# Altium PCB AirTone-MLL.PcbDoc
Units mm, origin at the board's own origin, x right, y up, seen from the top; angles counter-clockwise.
Board outline 33.13 x 51.18 mm, 2 copper layers (Top Layer, Bottom Layer); 97 components, 78 nets, 367 pads, 121 vias.
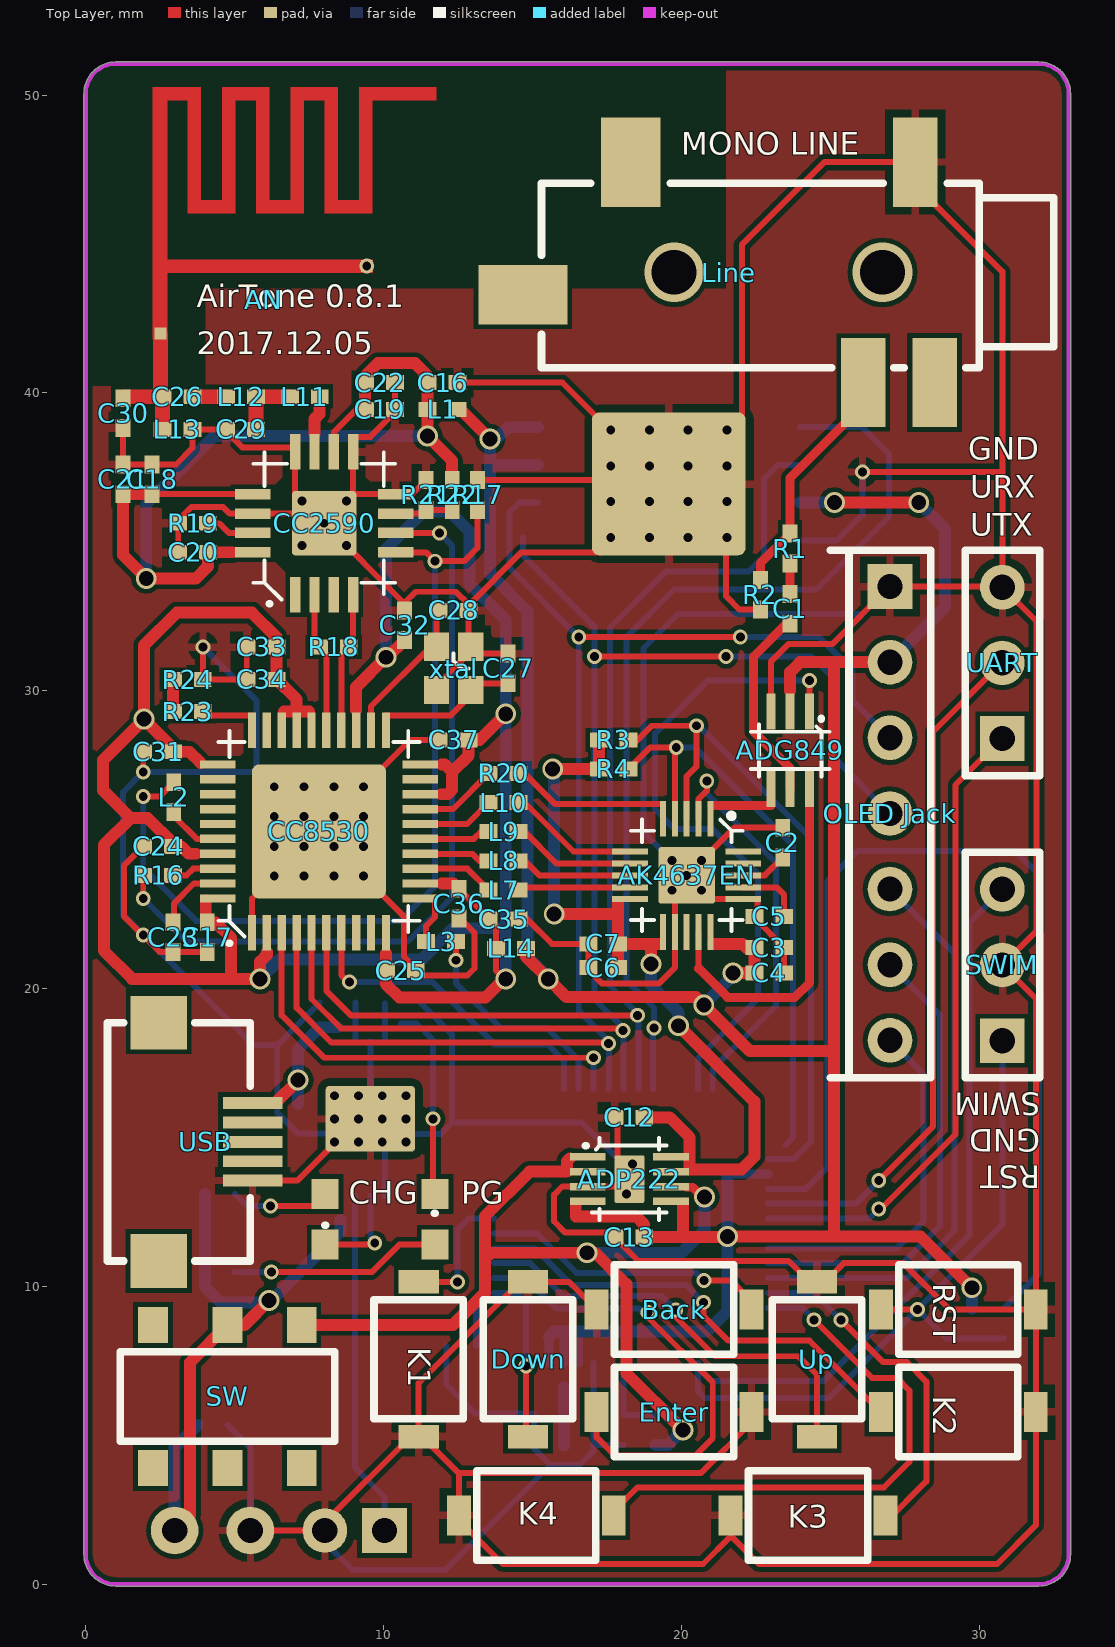
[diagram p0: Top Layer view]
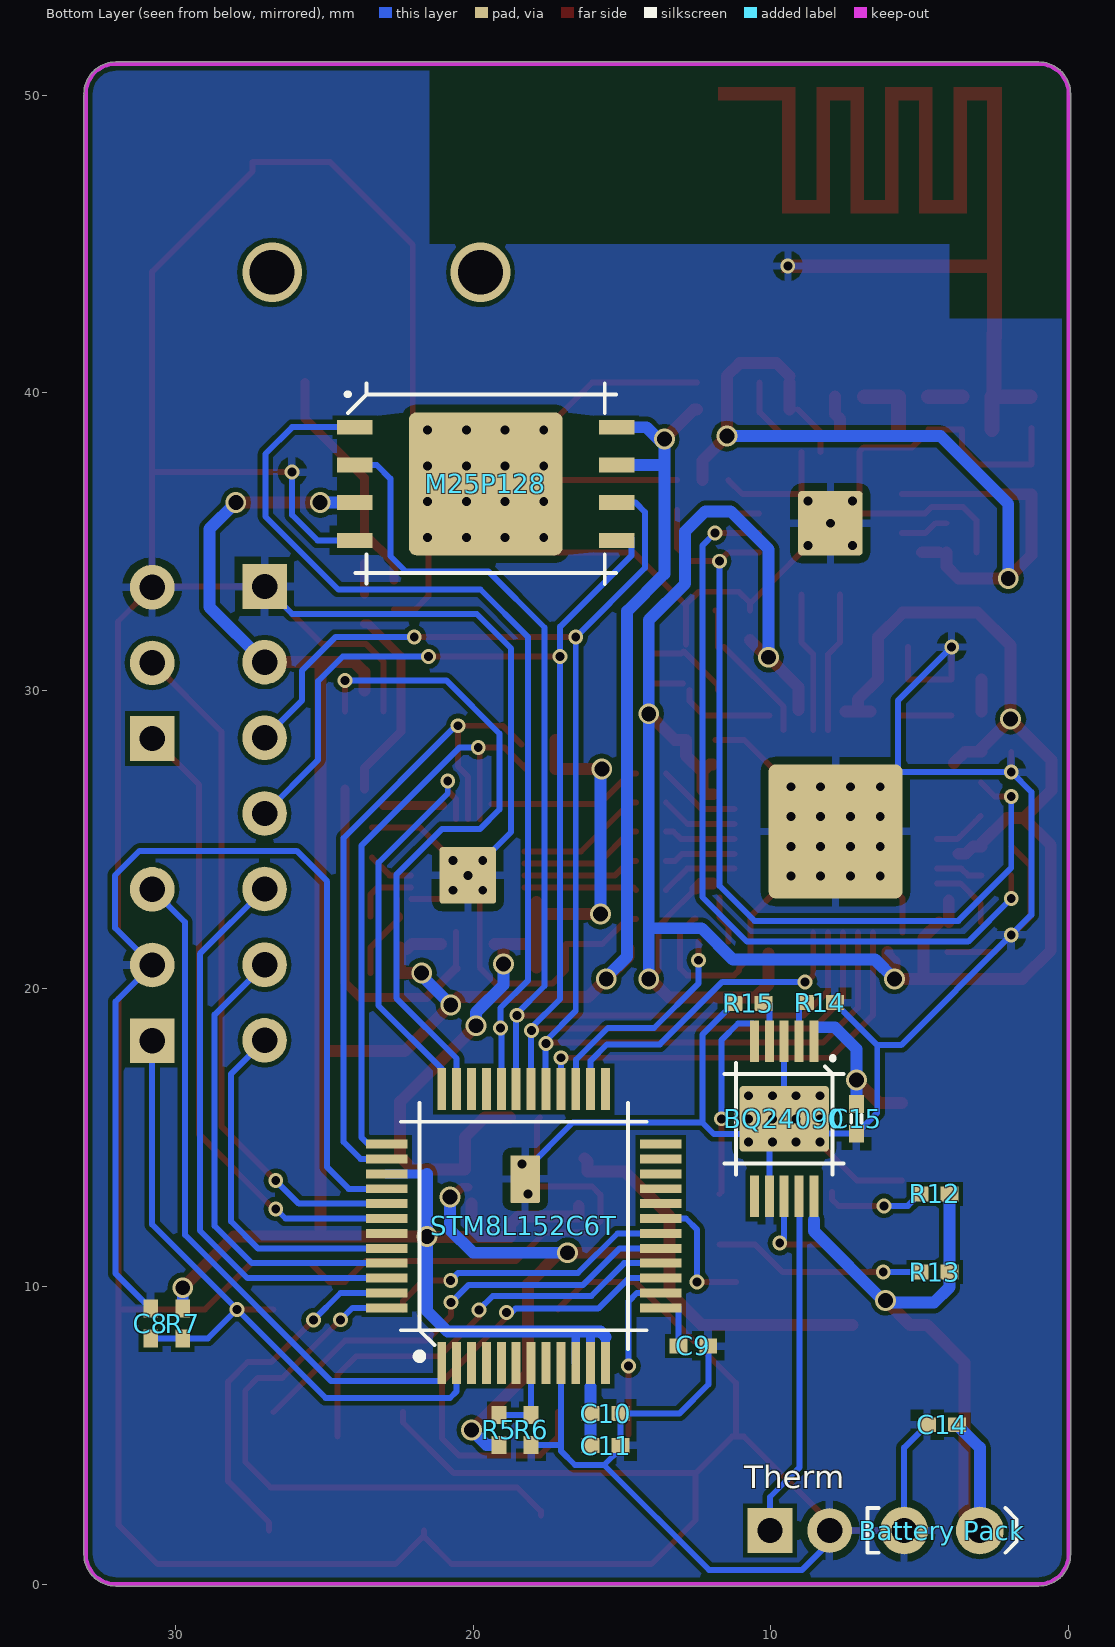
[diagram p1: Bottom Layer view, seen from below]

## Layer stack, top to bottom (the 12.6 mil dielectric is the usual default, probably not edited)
Top Solder: solder mask 0.0102, Solder Resist, Dk 3.5
Top Layer: signal copper 0.0356
Dielectric 1: dielectric 0.32, FR-4, Dk 4.8
Bottom Layer: signal copper 0.0356
Bottom Solder: solder mask 0.0102, Solder Resist, Dk 3.5

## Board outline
-0.065,1 -0.065,50 cw(c0,50) -0.06,50.025 cw(c0,50.05) -0.065,50.05 cw(c1,50.05) 1,51.115 32,51.115 cw(c32,50.05) 33.065,50.05 cw(c33,50.05) 33.06,50.025 cw(c33,50) 33.065,50 33.065,1 cw(c32,1) 32,-0.065 1,-0.065 cw(c1,1)

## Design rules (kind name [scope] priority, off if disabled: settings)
Clearance [All] p1: gap=0.16
Clearance poly [InPoly] p2: gap=2
ComponentClearance [All] p1: gap=-1 collisioncheckmode=3 verticalgap=0.254 showdistances=FALSE
HoleToHoleClearance [All] p1: gap=0.01 allowstackedmicrovias=TRUE
MinimumSolderMaskSliver [All] p1: minsoldermaskwidth=0.01
PlaneClearance [All] p1: clearance=0.58
PolygonConnect [All] p1: connectstyle=Relief reliefconductorwidth=0.254 reliefentries=4 polygonreliefangle="90 Angle" airgapwidth=0.254
RoutingVias [All] p1: holewidth=0.3 width=0.4 viastyle="Through Hole" minholewidth=0.3 minwidth=0.4 maxholewidth=5 maxwidth=6
SilkToSilkClearance [All] p1: silktosilkclearance=0
SilkToSolderMaskClearance [IsPad] p1: minsilkscreentomaskgap=0 clearancetoexposedcopper=TRUE
SolderMaskExpansion [All] p1: expansion=0.102
Width [All] p1: maxlimit=0.8 minlimit=0.1 preferedwidth=0.2
24 further rules are at their usual default settings.

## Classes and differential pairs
component class Audio: ADG849 AK4637EN C1 C2 C3 C4 C5 C6 C7 Line R1 R2 R3 R4
component class MCU: ADP222 Back "Battery Pack" BQ24090 C8 C9 C10 C11 C12 C13 C14 C15 CHG Down Enter K1 K2 K3 K4 M25P128 "OLED Jack" PG R5 R6 R7 R12 R13 R14 R15 RST STM8L152C6T SW SWIM Therm UART Up USB
component class RF: AN C16 C17 C18 C19 C20 C21 C22 C23 C24 C25 C26 C27 C28 C29 C30 C31 C32 C33 C34 C35 C36 C37 CC2590 CC8530 L1 L2 L3 L7 L8 L9 L10 L11 L12 L13 L14 R16 R17 R18 R19 R20 R21 R22 R23 R24 X1 xtal

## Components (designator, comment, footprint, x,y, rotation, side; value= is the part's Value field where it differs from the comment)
ADG849 "ADG849" ADG849 23.65,28 r180 top
ADP222 "ADP222ACPZ-1833-R7" ADP22x 18.25,13.6 r270 top
AK4637EN "AK4637EN" AK4637EN 20.175,23.8 r180 top
AN "Antenna" ANT_WIGGLE_1MM 2.5,42 r0 top
Back "Button" Button_3x4 19.75,9.225 r180 top
"Battery Pack" "Battery Pack" "Battery Jack small" 4.25,1.8 r0 bottom
BQ24090 "BQ24090" BQ24090 9.55,15.625 r0 bottom
C1 "Capacity SMD" "SMD 0402" 23.65,32.75 r90 top
C2 "Capacity SMD" "SMD 0402" 23.4,24.9 r90 top
C3 "Capacity SMD" "SMD 0402" 22.95,21.375 r0 top
C4 "Capacity SMD" "SMD 0402" 22.95,20.525 r0 top
C5 "Capacity SMD" "SMD 0402" 22.95,22.425 r180 top
C6 "Capacity SMD" "SMD 0402" 17.375,20.7 r180 top
C7 "Capacity SMD" "SMD 0402" 17.375,21.5 r180 top
C8 "Capacity SMD" "SMD 0402" 30.825,8.75 r270 bottom
C9 "Capacity SMD" "SMD 0402" 12.6,8 r0 bottom
C10 "Capacity SMD" "SMD 0402" 15.55,5.725 r0 bottom
C11 "Capacity SMD" "SMD 0402" 15.55,4.65 r0 bottom
C12 "Capacity SMD" "SMD 0402" 18.25,15.675 r180 top
C13 "Capacity SMD" "SMD 0402" 18.25,11.65 r0 top
C14 "Capacity SMD" "SMD 0402" 4.25,5.35 r180 bottom
C15 "Capacity SMD" "SMD 0402_silk" 7.125,15.625 r90 bottom
C16 "Capacity SMD" "SMD 0402" 11.975,40.35 r180 top
C17 "Capacity SMD" "SMD 0402" 4.075,21.725 r270 top
C18 "Capacity SMD" "SMD 0402" 2.225,37.1 r270 top
C19 "Capacity SMD" "SMD 0402" 9.875,39.45 r180 top
C20 "Capacity SMD" "SMD 0402" 3.6,34.65 r0 top
C21 "Capacity SMD" "SMD 0402" 1.25,37.1 r270 top
C22 "Capacity SMD" "SMD 0402" 9.875,40.35 r180 top
C23 "Capacity SMD" "SMD 0402" 2.925,21.725 r270 top
C24 "Capacity SMD" "SMD 0402" 2.425,24.775 r0 top
C25 "Capacity SMD" "SMD 0402" 10.575,20.6 r180 top
C26 "Capacity SMD" "SMD 0402" 3.075,39.875 r180 top
C27 "Capacity SMD" "SMD 0402" 14.175,30.75 r270 top
C28 "Capacity SMD" "SMD 0402" 12.35,32.7 r180 top
C29 "Capacity SMD" "SMD 0402" 5.212,38.775 r0 top
C30 "Capacity SMD" "SMD 0402" 1.25,39.325 r90 top
C31 "Capacity SMD" "SMD 0402" 2.425,27.95 r0 top
C32 "Capacity SMD" "SMD 0402" 10.7,32.2 r270 top
C33 "Capacity SMD" "SMD 0402" 5.9,31.475 r0 top
C34 "Capacity SMD" "SMD 0402" 5.9,30.383 r0 top
C35 "Capacity SMD" "SMD 0402" 14.025,22.329 r180 top
C36 "Capacity SMD" "SMD 0402" 12.525,22.85 r90 top
C37 "Capacity SMD" "SMD 0402" 12.35,28.35 r0 top
CC2590 "CC2590" CC2590 8,35.625 r90 top
CC8530 "CC8530" CC8530 7.825,25.275 r90 top
CHG "LED" LED_0603 8.025,12.25 r270 top
Down "Button" Button_3x4 14.85,7.55 r90 top
Enter "Button" Button_3x4 19.75,5.775 r0 top
K1 "Button" Button_3x4 11.175,7.55 r270 top
K2 "Button" Button_3x4 29.3,5.775 r0 top
K3 "Button" Button_3x4 24.25,2.3 r180 top
K4 "Button" Button_3x4 15.125,2.3 r180 top
L1 "Inductor SMD" "SMD 0402" 11.975,39.45 r180 top
L2 "Inductor SMD" "SMD 0402" 2.95,26.425 r90 top
L3 "Inductor SMD" "SMD 0402" 11.925,21.575 r0 top
L7 "Inductor SMD" "SMD 0402" 14.025,23.308 r180 top
L8 "Inductor SMD" "SMD 0402" 14.025,24.287 r180 top
L9 "Inductor SMD" "SMD 0402" 14.025,25.267 r180 top
L10 "Inductor SMD" "SMD 0402" 14.025,26.246 r180 top
L11 "Inductor SMD" "SMD 0402" 7.35,39.875 r0 top
L12 "Inductor SMD" "SMD 0402" 5.212,39.875 r180 top
L13 "Inductor SMD" "SMD 0402" 3.075,38.775 r180 top
L14 "Inductor SMD" "SMD 0402" 14.275,21.35 r180 top
Line "Audio Jack" "Audio Jack PJ-328" 30,44.05 r180 top
M25P128 "M25P128" M25P128 19.575,36.95 r180 bottom
"OLED Jack" "OLED Jack" "OLED Jack" 27,33.5 r0 top
PG "LED" LED_0603 11.725,12.25 r90 top
R1 "Resistor SMD" "SMD 0402" 23.65,34.775 r90 top
R2 "Resistor SMD" "SMD 0402" 22.65,33.225 r90 top
R3 "Resistor SMD" "SMD 0402" 17.725,28.35 r180 top
R4 "Resistor SMD" "SMD 0402" 17.725,27.375 r180 top
R5 "Resistor SMD" "SMD 0402" 19.125,5.175 r270 bottom
R6 "Resistor SMD" "SMD 0402" 18.05,5.175 r90 bottom
R7 "Resistor SMD" "SMD 0402" 29.75,8.75 r90 bottom
R12 "Resistor SMD" "SMD 0402" 4.5,13.1 r180 bottom
R13 "Resistor SMD" "SMD 0402" 4.5,10.475 r180 bottom
R14 "Resistor SMD" "SMD 0402" 8.35,19.525 r0 bottom
R15 "Resistor SMD" "SMD 0402" 10.75,19.5 r180 bottom
R16 "Resistor SMD" "SMD 0402" 2.425,23.8 r180 top
R17 "Resistor SMD" "SMD 0402" 13.15,36.575 r270 top
R18 "Resistor SMD" "SMD 0402" 8.325,31.475 r180 top
R19 "Resistor SMD" "SMD 0402" 3.6,35.625 r180 top
R20 "Resistor SMD" "SMD 0402" 14.025,27.225 r180 top
R21 "Resistor SMD" "SMD 0402" 11.425,36.575 r270 top
R22 "Resistor SMD" "SMD 0402" 12.3,36.575 r270 top
R23 "Resistor SMD" "SMD 0402" 3.425,29.3 r0 top
R24 "Resistor SMD" "SMD 0402" 3.425,30.375 r180 top
RST "Button" Button_3x4 29.3,9.225 r180 top
STM8L152C6T "STM8L152C6T" "STM LQFP48" 18.3,12.025 r180 bottom (schematic designator STM1)
SW "Switch" "Switch 2P2T" 4.75,6.3 r0 top
SWIM "Header_3x1" HEADER_3x1_2.54 30.775,18.25 r90 top
Therm "Thermistor" Header_2x1_2.00 9.025,1.8 r180 bottom
UART "Header_3x1" HEADER_3x1_2.54 30.775,28.395 r90 top
Up "Button" Button_3x4 24.55,7.55 r90 top
USB "USB Jack Mirco-B" "USB Micro-B" 5.275,14.85 r270 top
xtal "XTAL" xtal_3225_FA-128 12.35,30.75 r90 top

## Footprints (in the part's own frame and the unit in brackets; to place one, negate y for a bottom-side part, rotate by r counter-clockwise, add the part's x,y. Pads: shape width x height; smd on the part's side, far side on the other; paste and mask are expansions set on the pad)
ADG849 [mm]
  rect 0.3x1.2 smd paste+0 mask+0: 1(-0.65,-1.3) 2(0,-1.3) 3(0.65,-1.3) 4(0.65,1.3) 5(0,1.3) 6(-0.65,1.3)
  silkscreen extent -1.33,-1.07 1.33,0.87
ADP22x [mm]
  rect 0.25x1.2 smd mask+0: 1(-0.75,-1.4) 2(-0.25,-1.4) 3(0.25,-1.4) 4(0.75,-1.4) 5(0.75,1.4) 6(0.25,1.4) 7(-0.25,1.4) 8(-0.75,1.4)
  rrect10% 1.6x1 smd mask+0: 3(0,0)
  rrect10% 1.6x1 smd far side mask+0: 3(0,0)
  silkscreen extent -1.38,-1.48 1.38,1.25
AK4637EN [mm]
  rect 0.2x1.2 smd mask+0: 1(-0.8,-1.9) 2(-0.4,-1.9) 3(0,-1.9) 4(0.4,-1.9) 5(0.8,-1.9) 11(0.8,1.9) 12(0.4,1.9) 13(0,1.9) 14(-0.4,1.9) 15(-0.8,1.9)
  rect 1.2x0.2 smd mask+0: 6(1.9,-0.8) 7(1.9,-0.4) 8(1.9,0) 9(1.9,0.4) 10(1.9,0.8) 16(-1.9,0.8) 17(-1.9,0.4) 18(-1.9,0) 19(-1.9,-0.4) 20(-1.9,-0.8)
  rrect10% 1.9x1.9 smd mask+0: 12(0,0)
  rrect10% 1.9x1.9 smd far side mask+0: 12(0,0)
  silkscreen extent -1.88,-2.05 1.88,1.88
ANT_WIGGLE_1MM [mm]
  rect 0.4x0.4 smd: 1(0,0) 2(6.93,2.26)
  Top Layer region: 6.667,7.826 9.267,7.826 9.267,8.275 6.667,8.275
  Top Layer region: 6.667,4.024 7.117,4.024 7.117,8.275 6.667,8.275
  Top Layer region: 5.519,4.024 7.117,4.024 7.117,4.475 5.519,4.475
  Top Layer region: 5.519,4.024 5.969,4.024 5.969,8.277 5.519,8.277
  Top Layer region: 4.367,7.824 5.969,7.824 5.969,8.277 4.367,8.277
  Top Layer region: 4.367,4.024 4.818,4.024 4.818,8.274 4.367,8.274
  Top Layer region: 3.217,4.024 4.818,4.024 4.818,4.475 3.217,4.475
  Top Layer region: 3.217,4.024 3.668,4.024 3.668,8.274 3.217,8.274
  Top Layer region: 2.067,7.824 3.668,7.824 3.668,8.274 2.067,8.274
  Top Layer region: 2.067,4.026 2.517,4.026 2.517,8.274 2.067,8.274
  Top Layer region: 0.917,4.026 2.517,4.026 2.517,4.476 0.917,4.476
  Top Layer region: 0.917,4.026 1.363,4.026 1.363,8.279 0.917,8.279
  Top Layer region: -0.262,7.825 1.363,7.825 1.363,8.274 -0.262,8.274
  Top Layer region: 0.017,2.026 7.147,2.026 7.147,2.475 0.017,2.475
  Top Layer region: -0.262,-0.199 0.238,-0.199 0.238,8.274 -0.262,8.274
"Audio Jack PJ-328" [mm]
  rect 1.5x3 smd mask+0.1: 1(2.15,-3.7) 3(3.9,3.7) 5(1.5,3.7)
  rect 2x3 smd mask+0.1: 2(11.7,-3.7)
  rect 3x2 smd mask+0.1: 4(15.325,0.75)
  silkscreen extent -2.5,-3 14.7,3.2
"Battery Jack small" [mm]
  round 1.6 hole 0.85 paste+0 mask+0: 1(-1.27,0) 2(1.27,0)
  silkscreen extent -2.5,-0.75 2.5,0.75
BQ24090 [mm]
  rect 0.3x1.4 smd paste+0 mask+0: 1(-1,-2.6) 2(-0.5,-2.6) 3(0,-2.6) 4(0.5,-2.6) 5(1,-2.6) 6(1,2.6) 7(0.5,2.6) 8(0,2.6) 9(-0.5,2.6) 10(-1,2.6)
  rrect10% 3x2.2 smd far side paste+0 mask+0: 3(0,0)
  rrect10% 3x2.2 smd paste+0 mask+0: 3(0,0)
  silkscreen extent -2,-2.05 2,1.88
Button_3x4 [mm]
  rect 0.8x1.35 smd paste+0 mask+0: 1(-2.6,0) 2(2.6,0)
  silkscreen extent -2,-1.5 2,1.5
CC2590 [mm]
  rect 1.2x0.35 smd paste+0 mask+0: 1(-2.4,0.975) 2(-2.4,0.325) 3(-2.4,-0.325) 4(-2.4,-0.975) 9(2.4,-0.975) 10(2.4,-0.325) 11(2.4,0.325) 12(2.4,0.975)
  rect 0.35x1.2 smd paste+0 mask+0: 5(-0.975,-2.4) 6(-0.325,-2.4) 7(0.325,-2.4) 8(0.975,-2.4) 13(0.975,2.4) 14(0.325,2.4) 15(-0.325,2.4) 16(-0.975,2.4)
  rrect10% 2.16x2.16 smd paste+0 mask+0: 17(0,0)
  rrect10% 2.16x2.16 smd far side paste+0 mask+0: 17(0,0)
  silkscreen extent -2.7,-2.37 2.37,2.37
CC8530 [mm]
  rect 1.2x0.28 smd paste+0 mask+0: 1(-3.4,2.25) 2(-3.4,1.75) 3(-3.4,1.25) 4(-3.4,0.75) 5(-3.4,0.25) 6(-3.4,-0.25) 7(-3.4,-0.75) 8(-3.4,-1.25) 9(-3.4,-1.75) 10(-3.4,-2.25) 21(3.4,-2.25) 22(3.4,-1.75) 23(3.4,-1.25) 24(3.4,-0.75) 25(3.4,-0.25) 26(3.4,0.25) 27(3.4,0.75) 28(3.4,1.25) 29(3.4,1.75) 30(3.4,2.25)
  rect 0.28x1.2 smd paste+0 mask+0: 11(-2.25,-3.4) 12(-1.75,-3.4) 13(-1.25,-3.4) 14(-0.75,-3.4) 15(-0.25,-3.4) 16(0.25,-3.4) 17(0.75,-3.4) 18(1.25,-3.4) 19(1.75,-3.4) 20(2.25,-3.4) 31(2.25,3.4) 32(1.75,3.4) 33(1.25,3.4) 34(0.75,3.4) 35(0.25,3.4) 36(-0.25,3.4) 37(-0.75,3.4) 38(-1.25,3.4) 39(-1.75,3.4) 40(-2.25,3.4)
  rrect10% 4.5x4.5 smd paste+0 mask+0: 41(0,0)
  rrect10% 4.5x4.5 smd far side paste+0 mask+0: 41(0,0)
  silkscreen extent -3.75,-3.37 3.37,3.37
Header_2x1_2.00 [mm]
  rect 1.5x1.5 hole 0.85 paste+0 mask+0: 1(-1,0)
  round 1.5 hole 0.85 paste+0 mask+0: 2(1,0)
HEADER_3x1_2.54 [mm]
  rect 1.5x1.5 hole 0.85 paste+0 mask+0: 1(0,0)
  round 1.5 hole 0.85 paste+0 mask+0: 2(2.54,0) 3(5.08,0)
  silkscreen extent -1.25,-1.25 6.33,1.25
LED_0603 [mm]
  rect 1x0.9 smd paste+0 mask+0: 1(-0.85,0)
  rect 1x0.9 smd mask+0: 2(0.85,0)
  silkscreen extent 0.2,0 0.2,0.03
M25P128 [mm]
  rect 1.2x0.5 smd paste+0 mask+0: 1(-4.4,1.9) 2(-4.4,0.633) 3(-4.4,-0.633) 4(-4.4,-1.9) 5(4.4,-1.9) 6(4.4,-0.633) 7(4.4,0.633) 8(4.4,1.9)
  rrect10% 5.16x4.8 smd far side paste+0 mask+0: 4(0,0)
  rrect10% 5.16x4.8 smd paste+0 mask+0: 4(0,0)
  silkscreen extent -4.65,-3.37 4.38,3.37
"OLED Jack" [mm]
  rect 1.5x1.5 hole 0.85 paste+0 mask+0: 1(0,0)
  round 1.5 hole 0.85 paste+0 mask+0: 2(0,-2.54) 3(0,-5.08) 4(0,-7.62) 5(0,-10.16) 6(0,-12.7) 7(0,-15.24)
  silkscreen extent -2,-16.5 1.38,1.22
"SMD 0402" [mm]
  rect 0.6x0.5 smd paste+0 mask+0: 1(-0.5,0) 2(0.5,0)
"SMD 0402_silk" [mm]
  rect 0.6x0.5 smd paste+0 mask+0: 1(-0.5,0) 2(0.5,0)
  silkscreen extent -0.13,-0.18 0.13,0.18
"STM LQFP48" [mm] "48-Pin LQFP"
  rect 0.3x1.4 smd paste+0 mask+0: 1(-2.75,-4.6) 2(-2.25,-4.6) 3(-1.75,-4.6) 4(-1.25,-4.6) 5(-0.75,-4.6) 6(-0.25,-4.6) 7(0.25,-4.6) 8(0.75,-4.6) 9(1.25,-4.6) 10(1.75,-4.6) 11(2.25,-4.6) 12(2.75,-4.6) 25(2.75,4.6) 26(2.25,4.6) 27(1.75,4.6) 28(1.25,4.6) 29(0.75,4.6) 30(0.25,4.6) 31(-0.25,4.6) 32(-0.75,4.6) 33(-1.25,4.6) 34(-1.75,4.6) 35(-2.25,4.6) 36(-2.75,4.6)
  rect 1.4x0.3 smd paste+0 mask+0: 13(4.6,-2.75) 14(4.6,-2.25) 15(4.6,-1.75) 16(4.6,-1.25) 17(4.6,-0.75) 18(4.6,-0.25) 19(4.6,0.25) 20(4.6,0.75) 21(4.6,1.25) 22(4.6,1.75) 23(4.6,2.25) 24(4.6,2.75) 37(-4.6,2.75) 38(-4.6,2.25) 39(-4.6,1.75) 40(-4.6,1.25) 41(-4.6,0.75) 42(-4.6,0.25) 43(-4.6,-0.25) 44(-4.6,-0.75) 45(-4.6,-1.25) 46(-4.6,-1.75) 47(-4.6,-2.25) 48(-4.6,-2.75)
  silkscreen extent -4.13,-4.47 4.13,4.13
"Switch 2P2T" [mm]
  rect 1x1.2 smd: 1(-2.5,2.4) 3(2.5,2.4) 4(-2.5,-2.4) 5(0,-2.4) 6(2.5,-2.4)
  rect 1x1.2 smd mask+0.1: 2(0,2.4)
  silkscreen extent -3.6,-1.5 3.6,1.5
"USB Micro-B" [mm]
  rect 1.8x1.9 smd paste+0 mask+0: 0(-4,-2.825) 0(4,-2.825)
  rect 0.4x2 smd paste+0 mask+0: 1(-1.3,0.325) 2(-0.65,0.325) 3(0,0.325) 4(0.65,0.325) 5(1.3,0.325)
  silkscreen extent -4,-4.55 4,0.25
xtal_3225_FA-128 [mm]
  rect 0.95x0.85 smd paste+0 mask+0: 1(-0.725,-0.575) 2(0.725,-0.575) 3(0.725,0.575) 4(-0.725,0.575)
  silkscreen extent 0,-0.5 0.5,0

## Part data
ADP222: library part ADP222
Line: library part "Audio Jack PJ-328"
Therm: library part "Thermistor NTC"
USB: library part "USB Jack Micro-B"

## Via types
v1: diameter 0.5, hole 0.3, Top Layer to Bottom Layer, 95 vias
v2: diameter 0.7, hole 0.5, Top Layer to Bottom Layer, 24 vias
v3: diameter 2, hole 1.5, Top Layer to Bottom Layer, 2 vias

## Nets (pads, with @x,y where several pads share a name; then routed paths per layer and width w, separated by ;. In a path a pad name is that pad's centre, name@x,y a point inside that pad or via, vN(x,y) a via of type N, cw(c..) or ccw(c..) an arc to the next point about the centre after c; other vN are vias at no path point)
8530_CSN: CC8530.3 STM8L152C6T.28 | length 15
  Top Layer w0.2: CC8530.3 6.575,19.1 8,17.675 v1(17.05,17.675)
  Bottom Layer w0.2: STM8L152C6T.28 v1@17.05,17.8
8530_MISO: CC8530.6 M25P128.2 STM8L152C6T.31 | length 38.8
  Top Layer w0.2: CC8530.6 8.075,19.925 8.899,19.101 v1(18.526,19.101)
  Bottom Layer w0.2: v1(18.526,19.101) 18.526,19.109 18.543,19.126 18.55,19.133 17.6,20.083 17.6,32.125 19.475,34 22.25,34 22.775,34.525 22.775,37.125 23.233,37.583 M25P128.2 ; STM8L152C6T.31 18.552,16.627 18.552,19.123 v1@18.55,19.125
8530_MOSI: "OLED Jack.4" CC8530.5 M25P128.5 STM8L152C6T.30 | length 46.8
  Top Layer w0.2: CC8530.5 7.575,19.65 8.565,18.66 17.973,18.66 v1(18.042,18.591) ; v1(17.075,31.15) v1(21.5,31.15)
  Bottom Layer w0.2: M25P128.5@14.675,35.15 14.675,34.55 17.075,32.15 17.075,19.65 18.042,18.683 v1(18.042,18.591) ; STM8L152C6T.30 18.06,16.635 18.06,18.665 v1@18.05,18.675 ; v1(21.5,31.15) 24.375,31.15 25.2,30.325 25.2,27.68 27,25.88
8530_RSTN: L3.2 STM8L152C6T.27 | length 7.6
  Top Layer w0.2: v1(12.425,20.95) L3.2
  Bottom Layer w0.2: v1(12.425,20.95) 12.425,20.175 13.925,18.675 15.475,18.675 16.54,17.61 16.54,16.635 STM8L152C6T.27
8530_SCLK: "OLED Jack.3" CC8530.4 M25P128.6 STM8L152C6T.29 | length 48
  Top Layer w0.2: CC8530.4 7.075,19.35 8.24,18.185 17.515,18.185 v1(17.55,18.15) v1@17.55,18.25 ; v1(16.55,31.8) v1(21.975,31.8)
  Bottom Layer w0.2: M25P128.6 14.542,36.317 14.225,36 14.225,34.125 v1(16.55,31.8) 16.55,19.25 17.55,18.25 v1@17.55,18.23 ; STM8L152C6T.29 17.56,16.635 17.56,18.24 v1@17.55,18.23 ; v1(17.55,18.15) v1@17.55,18.23 ; v1(21.975,31.8) 24.625,31.8 25.75,30.675 25.75,29.67 27,28.42
+1.8V: ADP222.7 ADP222.8 AK4637EN.10 AK4637EN.11 C6.1 C7.1 C12.1 R3.2 R4.2 | length 26.9
  Top Layer w0.4: v2(15.675,27.375) R4.2 R3.2 ; v2(15.725,22.5) 17.85,22.5 ; C6.1 C7.1 ; AK4637EN.10@17.875,22.9 C7.1 ; C12.1 19.6,15.675 20.275,15 20.275,13.925 22.025,13.925 22.45,14.35 22.45,16.2 v2(19.9,18.75) ; v2(18.976,20.826) 18.976,21.499 18.975,21.5 ; AK4637EN.11@19.275,21.5 18.975,21.5 ; C7.1 18.975,21.5
  Bottom Layer w0.4: v2(15.725,22.5) v2@15.725,27.375 ; v2(18.976,20.826) 18.976,20.126 18.975,20.125 19.9,19.2 v2(19.9,18.75)
+3.3V: "OLED Jack.2" ADG849.2 ADP222.4 ADP222.5 AK4637EN.15 C3.1 C4.1 C10.2 C11.2 C13.2 L1.1 L14.1 M25P128.3 M25P128.7 M25P128.8 R7.2 STM8L152C6T.10 STM8L152C6T.11 STM8L152C6T.12 STM8L152C6T.39 | length 107.7
  Top Layer w0.4: L1.1 12.575,39.45 v2(13.575,38.45) ; L14.1 14.775,21.075 v2(15.525,20.325) 16.135,19.715 20.485,19.715 v2(20.75,19.45) 22.3,17.9 25.125,17.9 ; 16.45,12.7 16.45,12.35 18.475,12.35 18.75,12.075 C13.2 20.05,11.65 ; ADP222.5@20.05,12.775 20.05,11.65 ; 21.075,21.5 22.05,21.5 C3.1@22.225,21.325 ; v2@21.525,11.65 20.05,11.65 ; v2(21.55,11.675) 28.025,11.675 v2(29.75,9.95) ; v2(21.725,20.525) C4.1 C3.1 ; 23.65,30 23.65,30.625 23.985,30.96 25.125,30.96 ; 25.125,11.7 25.125,30.96 ; v2(25.133,36.317) v2(27.967,36.317) ; 27,30.96 25.125,30.96
  Bottom Layer w0.3: STM8L152C6T.12 15.55,8.3 ; STM8L152C6T.11 16.05,8.475 ; STM8L152C6T.10 16.55,8.475 ; 21.55,13.775 STM8L152C6T.39
  Bottom Layer w0.4: 13.592,37.583 M25P128.7 ; M25P128.8 14.175,38.85 13.575,38.25 13.575,33.925 14.825,32.675 14.825,21.075 15.525,20.375 v2(15.525,20.325) ; 15.55,8.3 15.725,8.475 16.05,8.475 16.55,8.475 20.85,8.475 21.55,9.175 v2(21.55,11.675) 21.55,13.775 ; C11.2 16.05,6.625 ; v2(20.75,19.45) 21.725,20.425 v2(21.725,20.525) ; M25P128.3 v2(25.133,36.317) ; 27,30.96 28.85,32.81 28.85,35.433 v2(27.967,36.317) ; R7.2 v2(29.75,9.95)
AVDD_CC2590: C16.2 C18.2 C19.2 C20.2 C21.2 C22.2 CC2590.10 CC2590.13 CC2590.16 L1.2 R22.1 | length 32.6
  Top Layer w0.2: C18.2 CC2590.13 ; CC2590.10 8.325,38.675 C19.2@9.1,39.45
  Top Layer w0.4: C18.2 C21.2 1.25,34.55 v2(2.025,33.775) 3.7,33.775 4.1,34.175 C20.2 ; C20.2@4.35,34.65 4.925,34.65 ; C19.2 C22.2 ; C22.2@9.375,40.575 9.8,41 11.05,41 11.475,40.575 L1.2 v2(11.475,38.55) 12.3,37.725 R22.1
  Bottom Layer w0.4: v2(2.025,33.775) 2.025,36.275 4.3,38.55 v2(11.475,38.55)
GND: "Battery Pack.2" "OLED Jack.1" ADG849.3 ADP222.3 AK4637EN.12 AK4637EN.16 AN.2 Back.2 BQ24090.3 BQ24090.7 C2.2 C3.2 C4.2 C5.2 C6.2 C7.2 C8.1 C9.1 C10.1 C11.1 C12.2 C13.1 C14.1 C15.1 C16.1 C17.2 C18.1 C19.1 C20.1 C21.1 C22.1 C23.2 C24.1 C25.1 C27.1 C28.1 C29.1 C30.1 C31.1 C32.1 C33.1 C34.1 C35.1 C36.1 C37.1 CC2590.8 CC2590.9 CC2590.12 CC2590.14 CC2590.17 CC8530.1 CC8530.41 Down.2 Enter.2 K1.2 K2.2 K3.2 K4.2 L13.1 Line.1 M25P128.4 R2.1 R6.1 R14.1 R15.1 R17.1 R19.2 R21.1 R24.1 RST.1 STM8L152C6T.9 STM8L152C6T.40 SWIM.2 Therm.2 UART.3 Up.2 USB.5 xtal.2 xtal.4 | length 388.8
  Top Layer w0.2: C30.1 C21.1 C18.1 3.025,37.6 3.575,38.15 L13.1 C29.1 4.713,38.713 5.25,38.175 6.875,38.175 CC2590.12 CC2590.17@7.025,36.6 ; C24.1 1.275,24.125 1.275,22.425 2.475,21.225 C23.2 C17.2 ; v1(1.925,27.275) C31.1 ; C20.1 R19.2 3.1,35.725 3.55,36.175 4.6,36.175 4.825,35.95 CC2590.14 CC2590.17@7.675,35.95 ; v1(3.925,31.475) R24.1 5.392,30.375 C34.1 C33.1 ; 5.52,1.8 Therm.2 8.025,2.075 10.9,4.95 K1.2 ; CC8530.1 5.575,23.025 v1(6.325,23.775) v1(7.325,24.775) CC8530.41@7.825,25.275 ; USB.5 7.1,13.55 8.925,15.375 BQ24090.3@8.925,15.625 ; v1(8,35.625) 10.7,32.925 C32.1 10.7,32.95 11.075,33.325 12.425,33.325 12.85,32.9 C28.1@12.85,32.875 ; CC2590.9@8.9,38.525 9.55,38.525 10.375,39.35 C19.1 C22.1 ; CC2590.9 8.975,36.6 CC2590.8 10.95,36.6 R21.1 ; xtal.4 11.775,30.175 xtal.2@12.925,31.325 ; C37.1 10.9,28.35 CC8530.41@7.825,25.275 ; C16.1 16,40.35 M25P128.4@19.275,37.075 ; C36.1 12.568,22.35 13.05,21.868 13.05,20.675 12.815,20.44 11.235,20.44 C25.1 11.075,20.675 10.675,21.075 10.675,22.425 CC8530.41@7.825,25.275 ; xtal.2@12.85,31.55 C28.1 C28.1@12.85,32.875 ; xtal.2@13,31.25 C27.1 ; R17.1 M25P128.4@19.275,37.075 ; C35.1 14.821,22.329 15.65,21.5 C7.2 C6.2 16.875,20.625 17.325,20.175 19.25,20.175 19.775,20.7 19.775,21.9 AK4637EN.12@19.775,23.4 ; Back.2 16.225,10.15 Down.2 14.575,10.15 11.175,6.75 K1.2 ; M25P128.4@17.275,34.65 14.625,34.65 C28.1@12.85,32.875 ; C12.2 17.85,15.575 ADP222.3@17.85,14.325 ; ADP222.3@18,13.35 16.85,13.35 16,13.35 15.725,13.075 15.725,12.175 16.1,11.8 17.6,11.8 C13.1 18.55,10.85 23.6,10.85 24.3,10.15 Up.2 24.825,10.15 25.45,10.775 27.45,10.775 29,9.225 RST.1 ; M25P128.4@19.4,36.95 M25P128.4@19.275,37.075 ; M25P128.4@19.45,37.075 M25P128.4@19.275,37.075 ; v1(20.175,23.8) 21.775,25.4 C2.2 ; AK4637EN.12@20.975,23 AK4637EN.16 ; M25P128.4@21.5,35.15 21.5,33.175 21.95,32.725 R2.1 ; K3.2@21.65,1.8 21.65,1.625 ; M25P128.4@22.025,38.9 22.025,44.975 24.8,47.75 27.4,47.75 27.4,47.45 30.775,44.075 30.775,37.35 ; Enter.2 22.35,5.425 20.65,3.725 12.525,3.725 ; C5.2@22.45,22.375 C3.2 C4.2 ; C5.2 22.55,22.525 AK4637EN.16@22.55,23 ; ADG849.3 23,30.975 23.6,31.575 25.075,31.575 27,33.5 UART.3@30.75,33.5 ; v1(26.075,37.35) 30.775,37.35 ; K1.2 11.3,4.95 12.525,3.725 ; 12.525,3.725 K4.2 12.525,2.15 14,0.675 20.725,0.675 21.65,1.6 21.65,1.625 ; 21.65,1.625 22.6,0.675 30.6,0.675 31.9,1.975 K2.2 RST.1 ; 30.775,37.35 UART.3 31.925,32.325 31.925,21.94 SWIM.2 31.9,19.665 RST.1
  Bottom Layer w0.2: v1(3.925,31.475) 5.725,29.675 CC8530.41@5.725,27.375 ; C14.1 5.52,4.58 5.52,1.8 ; v1(6.325,26.775) 5.825,27.275 v1(1.925,27.275) 1.25,26.6 1.25,22.475 v1(1.925,21.8) 5.625,18.1 6.425,18.1 ; R14.1 6.425,18.1 ; Therm.2 8.025,1.4 8.95,0.475 12.075,0.475 15.6,4 ; BQ24090.3@9.05,15.125 C15.1 6.425,15.825 6.425,18.1 ; BQ24090.3@9.55,15.625 BQ24090.3@9.55,18.225 ; BQ24090.7 BQ24090.3@10.05,14.85 ; BQ24090.3@10.05,15.025 BQ24090.3@10.05,15.125 ; BQ24090.3@10.062,15.112 11.912,15.112 12.3,15.5 ; R15.1 12.3,18.45 12.3,15.5 ; C9.1 12.1,6.7 13.075,5.725 C10.1 C11.1 15.05,4.55 15.6,4 ; STM8L152C6T.9 17.05,4.475 16.575,4 15.6,4 ; 17.075,4.675 R6.1 ; ADP222.3@18.25,13.9 16.65,15.5 12.3,15.5 ; v1(19.675,24.3) 18.725,25.25 18.725,31.425 19.875,32.575 26.075,32.575 27,33.5 ; STM8L152C6T.40 24.175,13.275 24.9,14 24.9,23.6 25.925,24.625 31.2,24.625 32.025,23.8 32.025,22.04 SWIM.2 32,19.565 32,10.425 C8.1 ; M25P128.4@23.975,35.05 25.225,35.05 26.075,35.9 v1(26.075,37.35)
  other v1: 18.15,13.1 18.35,14.1 8.35,14.85 9.15,14.85 9.95,14.85 10.75,14.85 8.35,15.625 9.15,15.625 9.95,15.625 10.75,15.625 8.35,16.4 9.15,16.4 9.95,16.4 10.75,16.4 19.675,23.3 20.675,23.3 7.325,23.775 8.325,23.775 9.325,23.775 20.675,24.3 6.325,24.775 8.325,24.775 9.325,24.775 6.325,25.775 7.325,25.775 8.325,25.775 9.325,25.775 7.325,26.775 8.325,26.775 9.325,26.775 7.25,34.875 8.75,34.875 17.625,35.15 18.925,35.15 20.225,35.15 21.525,35.15 17.625,36.35 18.925,36.35 20.225,36.35 21.525,36.35 7.25,36.375 8.75,36.375 17.625,37.55 18.925,37.55 20.225,37.55 21.525,37.55 17.625,38.75 18.925,38.75 20.225,38.75 21.525,38.75 9.43,44.26
IOVDD: C17.1 C24.2 C25.2 C31.2 C32.2 C33.2 C34.2 C35.2 C36.2 C37.2 CC8530.2 CC8530.10 CC8530.12 CC8530.18 CC8530.20 CC8530.23 CC8530.26 CC8530.27 CC8530.28 CC8530.31 CC8530.37 CC8530.40 L14.2 | length 84.1
  Top Layer w0.2: C36.2 C35.2@13.525,22.35 ; C35.2 13.775,22.079 L14.2 13.775,20.6 v2@14.05,20.325
  Top Layer w0.4: C31.2 2.925,28.075 v2(1.95,29.05) ; C31.2@2.95,27.95 3.475,27.95 CC8530.31@3.85,27.575 ; 3.7,24.525 3.45,24.525 3.2,24.775 C24.2 2.925,24.875 2.075,25.725 1.5,25.725 ; C17.1@4.025,22.225 CC8530.40@4.025,22.95 ; 4.35,22.225 4.875,21.7 4.875,20.325 ; 6.075,21.225 6.075,21.126 5.85,20.901 v2(5.85,20.325) 4.875,20.325 ; 6.65,29.3 7.075,29.3 ; 7.5,29.3 7.075,29.3 ; 9.075,29.35 9.075,30.125 v2(10.075,31.125) 10.125,31.125 C32.2 ; 10.075,21.175 C25.2 10.075,20.15 10.525,19.7 13.425,19.7 v2@14.05,20.325 ; 11.925,26.525 12.15,26.525 12.3,26.675 12.3,27.275 ; 11.95,23.525 12.35,23.525 C36.2 ; 11.95,27.525 12.05,27.525 12.3,27.275 ; v2(14.1,29.225) 13.225,28.35 C37.2 12.85,27.825 12.3,27.275 ; 1.5,25.725 0.6,24.825 0.6,21.275 1.55,20.325 4.875,20.325 ; 1.5,25.725 0.575,26.65 0.575,27.675 v2(1.95,29.05) ; v2(1.95,29.05) 1.95,31.525 3.05,32.625 5.575,32.625 6.4,31.8 C33.2 C34.2 7.075,29.708 7.075,29.3
  Bottom Layer w0.4: v2(5.85,20.325) 6.5,20.975 11.275,20.975 12.325,22.025 14.075,22.025 ; v2(10.075,31.125) 10.075,34.75 11.35,36.025 12.2,36.025 12.875,35.35 12.875,33.6 14.1,32.375 v2(14.1,29.225) v2(14.1,20.325)
NetADG849_1: ADG849.1 STM8L152C6T.35 | length 21.9
  Top Layer w0.2: ADG849.1 v1(24.3,30.35)
  Bottom Layer w0.2: STM8L152C6T.35 20.55,17.65 22.575,19.675 22.575,23.825 21.05,25.35 19.775,25.35 19.115,26.01 19.115,28.565 20.9,30.35 v1(24.3,30.35)
NetADG849_4: ADG849.4 AK4637EN.1 | length 2
  Top Layer w0.3: AK4637EN.1@21.025,26.15 ADG849.4@23,26.15
NetADG849_5: ADG849.5 C1.1 | length 6.6
  Top Layer w0.3: ADG849.5 23.65,27.4 22.425,28.625 22.425,31.15 23.525,32.25 C1.1
NetADG849_6: ADG849.6 AK4637EN.14 | length 12.1
  Top Layer w0.2: 20.575,20.675 AK4637EN.14
  Top Layer w0.3: 20.575,20.675 21.55,19.7 23.8,19.7 24.3,20.2 ADG849.6
NetAK4637EN_2: AK4637EN.2 STM8L152C6T.36 | length 13.6
  Top Layer w0.2: AK4637EN.2 20.575,26.368 20.85,26.643 v1(20.85,26.975)
  Bottom Layer w0.2: v1(20.85,26.975) 20.85,26.55 23.175,24.225 23.175,19.425 21.05,17.3 STM8L152C6T.36
NetAK4637EN_3: AK4637EN.3 R3.1 STM8L152C6T.38 | length 22.9
  Top Layer w0.2: R3.1@18.375,28.2 19,28.825 v1(20.5,28.825) 20.5,27.45 20.175,27.125 AK4637EN.3
  Bottom Layer w0.2: v1(20.5,28.825) 20.575,28.825 24.35,25.05 24.35,14.85 23.775,14.275 STM8L152C6T.38
NetAK4637EN_4: AK4637EN.4 R4.1 STM8L152C6T.37 | length 19.7
  Top Layer w0.2: R4.1 18.95,28.1 v1(19.825,28.1) ; R4.1@18.225,27.512 R4.1@18.237,27.5 ; AK4637EN.4 v1@19.775,28.05
  Bottom Layer w0.2: v1(19.825,28.1) 20.446,28.1 23.75,24.796 23.75,15 STM8L152C6T.37@23.5,14.75
NetAK4637EN_5: AK4637EN.5 R20.1 | length 5.3
  Top Layer w0.2: R20.1 14.725,27.225 15.75,26.2 AK4637EN.5@19.375,26.2
NetAK4637EN_6: AK4637EN.6 L10.1 | length 4.4
  Top Layer w0.2: L10.1 14.729,26.246 16.375,24.6 AK4637EN.6
NetAK4637EN_7: AK4637EN.7 L9.1 | length 4.2
  Top Layer w0.2: L9.1 14.733,25.267 15.8,24.2 AK4637EN.7
NetAK4637EN_8: AK4637EN.8 L8.1 | length 4
  Top Layer w0.2: L8.1 14.737,24.287 15.225,23.8 AK4637EN.8
NetAK4637EN_9: AK4637EN.9 L7.1 | length 3.8
  Top Layer w0.2: L7.1 14.617,23.4 AK4637EN.9
NetAK4637EN_17: AK4637EN.17 C5.1 | length 2.2
  Top Layer w0.2: AK4637EN.17 23.2,23.4 23.45,23.15 C5.1
NetAK4637EN_18: AK4637EN.18 C2.1 | length 1.6
  Top Layer w0.2: AK4637EN.18 22.8,23.8 C2.1
NetAN_1: AN.1 C26.2 C30.2 L13.2 | length 4.4
  Top Layer w0.5: C30.2@1.3,39.875 C26.2 L13.2 ; C26.2@2.5,39.95 AN.1
"NetBattery Pack_1": "Battery Pack.1" BQ24090.10 C14.2 R12.2 R13.2 SW.2 | length 22.5
  Top Layer w0.4: 2.98,1.8 3.5,2.32 3.5,7.45 SW.2 5.325,8.7 v2(6.15,9.525)
  Bottom Layer w0.4: 2.98,1.8 2.98,4.58 C14.2 ; R12.2 R13.2 4,9.975 4.525,9.45 6.15,9.45 8.55,11.85 8.55,12.225
NetBQ24090_1: BQ24090.1 C15.2 USB.1 | length 5.3
  Top Layer w0.4: USB.1 6.35,16.15 v2(7.125,16.925)
  Bottom Layer w0.4: C15.2 v2(7.125,16.925) 7.125,17.975 7.85,18.7 BQ24090.1@8.45,18.7
NetBQ24090_2: BQ24090.2 R14.2 | length 1.3
  Bottom Layer w0.2: BQ24090.2 R14.2@9.05,19.525
NetBQ24090_4: BQ24090.4 R15.2 | length 1.3
  Bottom Layer w0.2: BQ24090.4 R15.2@10.05,19.5
NetBQ24090_5: BQ24090.5 PG.2 | length 6.5
  Top Layer w0.2: v1(11.65,15.625) 11.65,13.175 PG.2
  Bottom Layer w0.2: BQ24090.5@10.575,18.825 11.1,18.825 11.65,18.275 v1(11.65,15.625)
NetBQ24090_8: BQ24090.8 CHG.2 | length 3.3
  Top Layer w0.2: CHG.2 9.65,11.4 v1(9.7,11.45)
  Bottom Layer w0.2: BQ24090.8 9.55,11.6 v1(9.7,11.45)
NetBQ24090_9: BQ24090.9 Therm.1 | length 11.6
  Bottom Layer w0.2: BQ24090.9 9.04,13.015 9.04,3.91 10.025,2.925 Therm.1
NetC1_2: C1.2 R1.1 | length 1
  Top Layer w0.3: C1.2 R1.1
NetC9_2: C9.2 STM8L152C6T.13 | length 1.3
  Bottom Layer w0.2: C9.2 STM8L152C6T.13@13.1,9.3
NetC23_1: C23.1 CC8530.39 | length 2.4
  Top Layer w0.2: C23.1@2.95,22.225 2.95,22.85 3.625,23.525 CC8530.39
NetC26_1: C26.1 L12.2 | length 1.1
  Top Layer w0.5: C26.1 L12.2
NetC27_2: C27.2 CC8530.21 xtal.1 | length 4.5
  Top Layer w0.2: CC8530.21@10.05,29.175 12.25,29.175 12.725,29.65 xtal.1@12.725,30.025 ; xtal.1@12.95,30.25 C27.2
NetC28_2: C28.2 CC8530.22 xtal.3 | length 4.9
  Top Layer w0.2: CC8530.22 9.575,29.475 xtal.3@11.575,31.475 ; xtal.3 11.775,32.625 C28.2
NetC29_2: C29.2 L11.1 L12.1 | length 2.2
  Top Layer w0.5: C29.2 L12.1 L11.1
NetCC2590_2: CC2590.2 CC8530.25 R18.2 | length 4.7
  Top Layer w0.2: CC2590.2 7.675,31.625 8.075,31.225 CC8530.25
NetCC2590_4: CC2590.4 CC8530.24 R18.1 | length 4.7
  Top Layer w0.2: CC8530.24 8.575,31.225 8.975,31.625 CC2590.4
NetCC2590_5: CC2590.5 L2.2 R17.2 | length 29.9
  Top Layer w0.2: v1(1.925,26.45) 2.475,26.45 L2.2 ; CC2590.5 11.425,34.65 v1(11.725,34.35) 12.7,34.35 13.15,34.8 R17.2
  Bottom Layer w0.2: v1(1.925,26.45) 1.925,24.05 3.7,22.275 10.55,22.275 11.725,23.45 v1(11.725,34.35)
NetCC2590_6: CC2590.6 R16.2 | length 26.2
  Top Layer w0.2: v1(1.925,23.025) R16.2 ; CC2590.6 v1(11.875,35.3)
  Bottom Layer w0.2: v1(1.925,23.025) 3.375,21.575 10.8,21.575 12.3,23.075 12.3,34.875 v1(11.875,35.3)
NetCC2590_7: CC2590.7 R21.2 R22.2 | length 1.8
  Top Layer w0.2: CC2590.7 R21.2@11.3,35.95 ; R21.2 R22.2
NetCC2590_11: CC2590.11 L11.2 | length 1.3
  Top Layer w0.4: 7.675,38.625 7.675,39.125 7.85,39.3 L11.2
NetCC2590_15: CC2590.15 R19.1 | length 1.6
  Top Layer w0.2: R19.1 4.475,35.625 4.8,35.3 CC2590.15
NetCC8530_7: CC8530.7 STM8L152C6T.26 | length 11
  Top Layer w0.2: CC8530.7 8.575,20.45 8.8,20.225 v1(8.85,20.225)
  Bottom Layer w0.2: v1(8.85,20.225) 11.625,20.225 13.725,18.125 15.5,18.125 16.05,17.575 STM8L152C6T.26
NetCC8530_11: CC8530.11 L3.1 | length 1.6
  Top Layer w0.2: L3.1 11.425,22.1 11.721,22.396 CC8530.11@11.721,23.05
NetCC8530_13: CC8530.13 L7.2 | length 2.6
  Top Layer w0.2: CC8530.13 12.808,24.025 L7.2
NetCC8530_14: CC8530.14 L8.2 | length 2.4
  Top Layer w0.2: CC8530.14 12.975,24.525 13.213,24.287 L8.2
NetCC8530_15: CC8530.15 L9.2 | length 2.4
  Top Layer w0.2: CC8530.15 13.025,25.025 13.267,25.267 L9.2
NetCC8530_16: CC8530.16 L10.2 | length 2.6
  Top Layer w0.2: CC8530.16 12.8,25.525 13.521,26.246 L10.2
NetCC8530_17: CC8530.17 R20.2 | length 2.8
  Top Layer w0.2: CC8530.17 12.325,26.025 R20.2
NetCC8530_30: CC8530.30 R23.2 | length 1.7
  Top Layer w0.2: R23.2@3.925,29.175 CC8530.30@5.6,29.175
NetCC8530_36: CC8530.36 L2.1 | length 1.8
  Top Layer w0.2: L2.1@2.95,25.8 3.144,25.606 3.531,25.219 3.725,25.025 CC8530.36
NetCC8530_38: CC8530.38 R16.1 | length 1.6
  Top Layer w0.2: R16.1 3.375,23.8 3.6,24.025 CC8530.38
NetCHG_1: CHG.1 R12.1 | length 3.5
  Top Layer w0.2: v1(6.2,12.7) 7.725,12.7 7.95,12.925 CHG.1@7.95,13.175
  Bottom Layer w0.2: R12.1 5.4,12.7 v1(6.2,12.7)
NetLine_3: Line.3 R1.2 R2.2 | length 7.9
  Top Layer w0.3: R2.2 22.65,34.275 R1.2 23.65,37.15 25.65,39.15 Line.3@25.65,40.35
NetPG_1: PG.1 R13.1 | length 7.1
  Top Layer w0.2: v1(6.225,10.475) 9.6,10.475 10.525,11.4 PG.1
  Bottom Layer w0.2: R13.1 v1(6.225,10.475)
NetR5_1: R5.1 R6.2 STM8L152C6T.7 | length 2.8
  Bottom Layer w0.2: STM8L152C6T.7 R6.2 R5.1
NetR23_1: R23.1 R24.2 | length 1.1
  Top Layer w0.4: R23.1 R24.2
SPI_OLED_SCN: "OLED Jack.7" STM8L152C6T.44 | length 12.1
  Bottom Layer w0.2: STM8L152C6T.44 27.225,11.275 28.125,12.175 28.125,17.135 27,18.26
STM8_KEY_1: K1.1 STM8L152C6T.19 | length 4.4
  Top Layer w0.2: K1.1 v1(12.475,10.15)
  Bottom Layer w0.2: v1(12.475,10.15) 12.475,11.9 12.85,12.275 STM8L152C6T.19
STM8_KEY_2: K2.1 STM8L152C6T.17 | length 15.5
  Top Layer w0.2: v1(20.737,9.462) 20.737,9.013 21.575,8.175 24.3,8.175 K2.1
  Bottom Layer w0.2: STM8L152C6T.17 15.075,11.275 16.3,10.05 20.15,10.05 v1(20.737,9.462)
STM8_KEY_3: K3.1 STM8L152C6T.47 | length 12.1
  Top Layer w0.2: v1(25.362,8.862) 26.775,7.45 27.575,7.45 28.225,6.8 28.225,3.45 26.85,2.075 K3.1@26.85,1.8
  Bottom Layer w0.2: STM8L152C6T.47 24.45,9.775 v1(25.362,8.862)
STM8_KEY_4: K4.1 STM8L152C6T.48 | length 19.1
  Top Layer w0.2: K4.1 17.725,2.45 18.525,3.25 26.8,3.25 27.65,4.1 27.65,6.5 27.225,6.925 26.4,6.925 v1(24.45,8.875)
  Bottom Layer w0.2: STM8L152C6T.48 24.05,9.275 v1(24.45,8.875)
STM8_KEY_BACK: Back.1 STM8L152C6T.18 | length 9.9
  Top Layer w0.2: v1(20.75,10.2) 21.65,10.2 22.35,9.5 Back.1
  Bottom Layer w0.2: STM8L152C6T.18 15.15,11.775 16.475,10.45 20.5,10.45 v1(20.75,10.2)
STM8_KEY_DOWN: Down.1 STM8L152C6T.14 | length 5.7
  Top Layer w0.2: Down.1@14.775,5.025 v1(14.775,7.325)
  Bottom Layer w0.2: STM8L152C6T.14 14.5,9.775 14.775,9.5 v1(14.775,7.325)
STM8_KEY_ENTER: Enter.1 STM8L152C6T.15 | length 16
  Top Layer w0.2: Enter.1 17.15,4.925 17.75,4.325 20.475,4.325 21.05,4.9 21.05,6.775 18.875,8.95 v1(18.875,9.125)
  Bottom Layer w0.2: STM8L152C6T.15 14.775,10.275 15.8,9.25 18.575,9.25 18.7,9.125 v1(18.875,9.125)
STM8_KEY_UP: STM8L152C6T.16 Up.1 | length 14.6
  Top Layer w0.2: v1(19.806,9.206) 19.806,8.969 21.125,7.65 23.925,7.65 24.55,7.025 Up.1
  Bottom Layer w0.2: STM8L152C6T.16 14.925,10.775 16.025,9.675 19.337,9.675 v1(19.806,9.206)
STM8_M25P_SCN: M25P128.1 STM8L152C6T.32 | length 31.5
  Bottom Layer w0.2: STM8L152C6T.32 v1@19.05,18.675 ; v1(19.076,18.676) 19.076,19.349 18.15,20.275 18.15,31.8 19.75,33.4 24.525,33.4 26.975,35.85 26.975,37.95 26.075,38.85 M25P128.1
STM8_OLED_D/C: "OLED Jack.6" STM8L152C6T.45 | length 15.8
  Bottom Layer w0.2: STM8L152C6T.45 27.425,10.775 28.675,12.025 28.675,19.125 27,20.8
STM8_OLED_RST: "OLED Jack.5" STM8L152C6T.46 | length 19.3
  Bottom Layer w0.2: STM8L152C6T.46 27.575,10.275 29.175,11.875 29.175,21.165 27,23.34
STM8_RST: C8.2 R7.1 RST.2 STM8L152C6T.2 SWIM.1 | length 24.4
  Top Layer w0.2: RST.2 v1(27.925,9.225)
  Bottom Layer w0.2: STM8L152C6T.2 20.55,6.475 20.775,6.25 24.95,6.25 v1(27.925,9.225) ; SWIM.1 30.775,12.075 v1(27.925,9.225) ; C8.2 R7.1 28.9,8.25 v1(27.925,9.225)
STM8_SWIM: STM8L152C6T.1 SWIM.3 | length 22.7
  Bottom Layer w0.2: STM8L152C6T.1@21.025,6.825 24.775,6.825 29.675,11.725 29.675,22.23 SWIM.3
"SYSTEM LOAD": ADP222.1 ADP222.2 ADP222.6 R5.2 SW.3 | length 31
  Top Layer w0.3: ADP222.6@20.175,13.325 20.375,13.325 20.7,13 v2(20.775,13)
  Top Layer w0.4: SW.3 12.325,8.7 13.4,9.775 13.4,10.92 ; 13.4,10.975 13.4,12.35 14.9,13.85 16.15,13.85 16.15,14.2 16.25,14.3 ; 13.505,11.025 13.605,11.125 v2(16.825,11.125) 17.1,11.125 18.15,10.075 18.15,7.075 v2(20.05,5.175)
  Bottom Layer w0.4: v2(16.825,11.125) 20,11.125 20.775,11.9 v2(20.775,13) ; R5.2 19.55,4.675 v2(20.05,5.175)
USART_RX: STM8L152C6T.41 UART.2 | length 23.2
  Top Layer w0.2: v1(26.625,13.55) 28.45,15.375 28.45,28.63 UART.2@30.775,30.955
  Bottom Layer w0.2: STM8L152C6T.41 25.85,12.775 v1(26.625,13.55)
USART_TX: STM8L152C6T.42 UART.1 | length 21.4
  Top Layer w0.2: v1(26.625,12.6) 26.7,12.6 29.2,15.1 29.2,26.84 UART.1@30.775,28.415
  Bottom Layer w0.2: STM8L152C6T.42 26.3,12.275 v1(26.625,12.6)
pads on no net: AK4637EN.13 AK4637EN.19 AK4637EN.20 BQ24090.6 CC2590.1 CC2590.3 CC8530.8 CC8530.9 CC8530.19 CC8530.29 CC8530.32 CC8530.33 CC8530.34 CC8530.35 Line.2 Line.4 Line.5 STM8L152C6T.3 STM8L152C6T.4 STM8L152C6T.5 STM8L152C6T.6 STM8L152C6T.8 STM8L152C6T.20 STM8L152C6T.21 STM8L152C6T.22 STM8L152C6T.23 STM8L152C6T.24 STM8L152C6T.25 STM8L152C6T.33 STM8L152C6T.34 STM8L152C6T.43 SW.1 SW.4 SW.5 SW.6 USB.0 USB.2 USB.3 USB.4
copper on no net:
  other v3: 19.75,44.05 26.75,44.05

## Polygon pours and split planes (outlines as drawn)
GND on Bottom Layer "GND" (solid, pour order 16): 0,0 33,0 33,51 0,51
GND on Top Layer "GND" (solid, pour order 18): 0,0 33,0 33,51 -0.06,51

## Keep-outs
Keep-Out Layer:
  lines w0.13: 0,50 0,1 ccw(c1,1) 1,0 32,0 ccw(c32,1) 33,1 33,50 ; 0,50.05 cw(c1,50.05) 1,51.05 32,51.05 cw(c32,50.05) 33,50.05

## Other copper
Top Layer:
  pour cut-out: 6.2,34.475 6.85,33.825 9.15,33.825 9.8,34.475 9.8,36.775 9.15,37.425 6.85,37.425 6.2,36.775
  pour cut-out: 17.45,12.725 17.45,14.475 17.75,14.4 18.75,14.4 19.05,14.475 19.05,12.725 18.75,12.8 17.75,12.8
  pour cut-out: 5.025,22.885 5.435,22.475 10.215,22.475 10.625,22.885 10.625,27.665 10.215,28.075 5.435,28.075 5.025,27.665
  pour cut-out: 19.275,22.5 18.875,22.9 18.875,24.7 19.275,25.1 21.075,25.1 21.475,24.7 21.475,22.9 21.075,22.5
  pour cut-out: -0.06,43.5 -0.065,40.225 4.025,40.225 4.025,43.5 21.5,43.5 21.5,51 11.95,51 -0.06,51 -0.06,47
Bottom Layer:
  pour cut-out: -0.065,42.5 4,42.5 4,45 21.475,45 21.475,51 11.95,51 -0.065,51
  pour cut-out: 14.575,34.8 16.995,34.55 22.155,34.55 24.575,34.8 24.575,39.1 22.155,39.35 16.995,39.35 14.575,39.1
  pour cut-out: 8.4,17.525 8.05,16.725 8.05,14.525 8.4,13.725 10.7,13.725 11.05,14.525 11.05,16.725 10.7,17.525

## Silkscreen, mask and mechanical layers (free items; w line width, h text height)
Top Overlay:
  text "MONO LINE" at 20,48 h0.76
  text "AirTone 0.8.1" at 3.725,42.875 h0.76
  text "2017.12.05" at 3.725,41.3 h0.76
  text "GND" at 29.625,37.75 h0.76
  text "URX" at 29.7,36.475 h0.76
  text "UTX" at 29.7,35.208 h0.76
  text "SWIM" at 32.05,16.5 h0.76 r180
  text "GND" at 32.05,15.275 h0.76 r180
  text "RST" at 32.05,14.05 h0.76 r180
